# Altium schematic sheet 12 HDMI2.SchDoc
size 297 x 209 mm
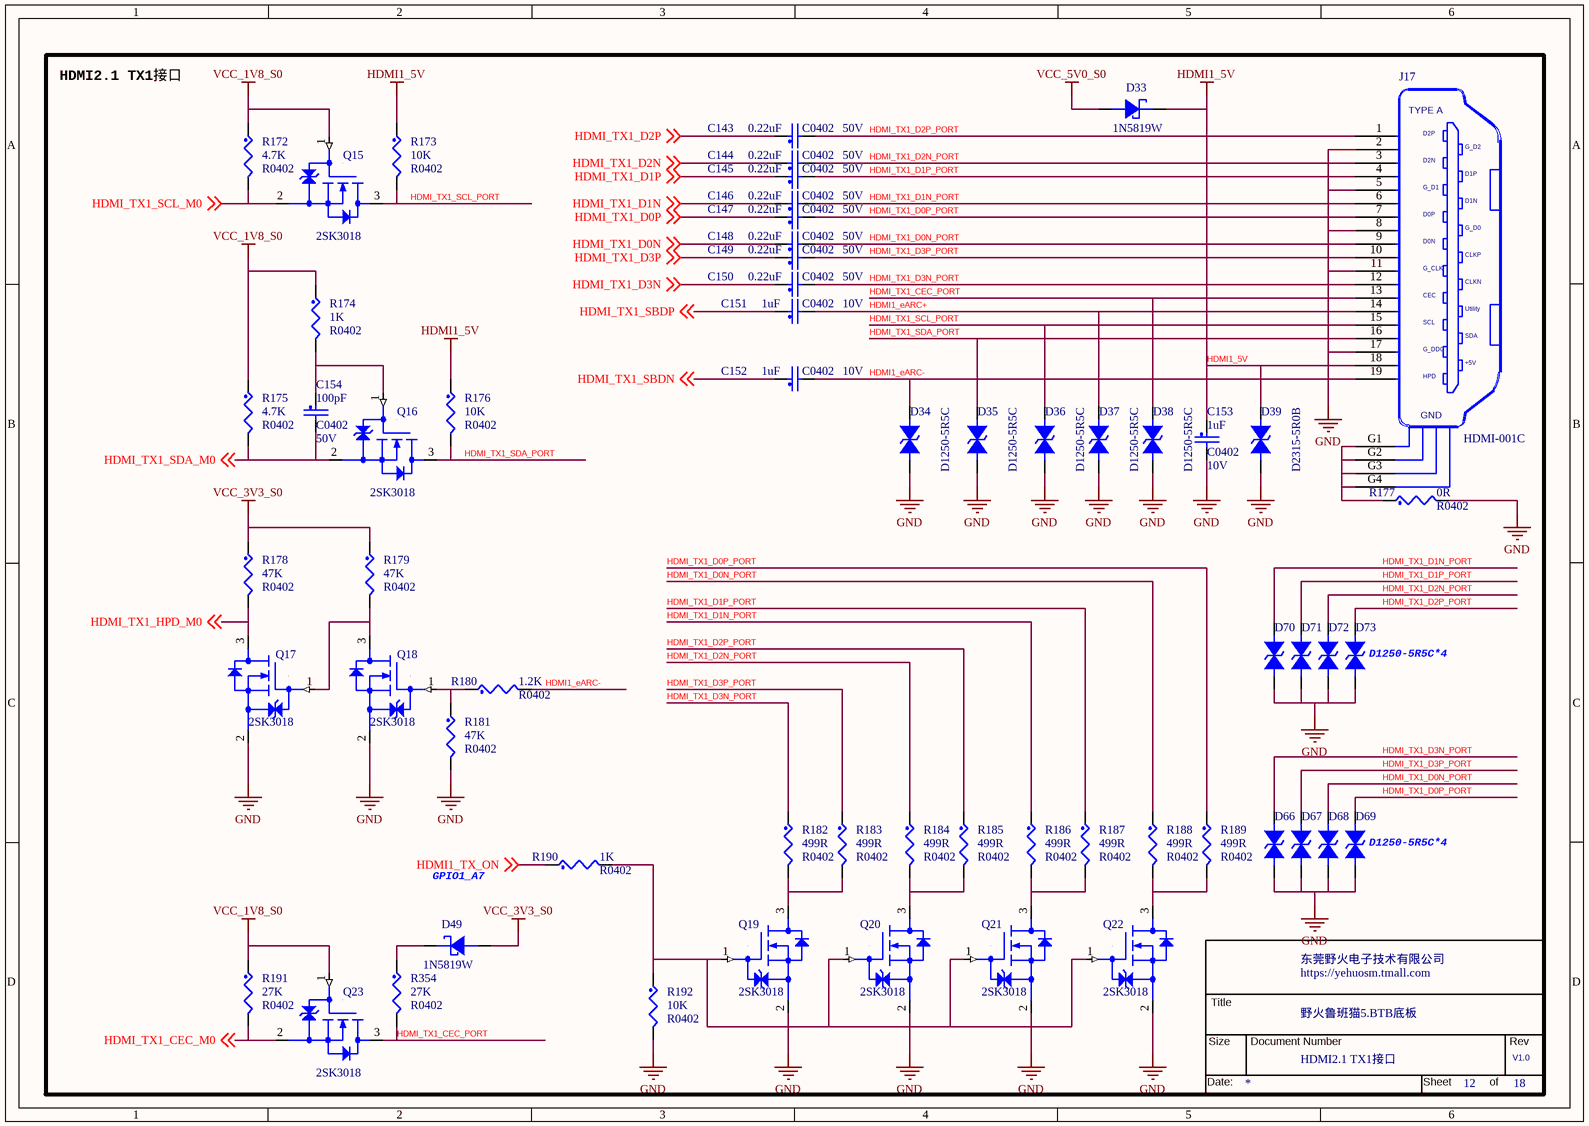
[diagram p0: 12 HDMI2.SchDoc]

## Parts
*  Doc: HDMI2.1 TX1接口  RevCode: V1.0  Title: 野火鲁班猫5.BTB底板  OrgName: 东莞野火电子技术有限公司  Page Number: 12  Page Count: 18  (hidden comment: TitleBlock_YHSCH)  (graphical)
C143  0.22uF  Voltage: 50V  [C0402]
C144  0.22uF  Voltage: 50V  [C0402]
C145  0.22uF  Voltage: 50V  [C0402]
C146  0.22uF  Voltage: 50V  [C0402]
C147  0.22uF  Voltage: 50V  [C0402]
C148  0.22uF  Voltage: 50V  [C0402]
C149  0.22uF  Voltage: 50V  [C0402]
C150  0.22uF  Voltage: 50V  [C0402]
C151  1uF  Voltage: 10V  [C0402]
C152  1uF  Voltage: 10V  [C0402]
C153  1uF  Voltage: 10V  [C0402]
C154  100pF  Voltage: 50V  [C0402]
D33  1N5819W  [SOD-123]
D34  D1250-5R5C  [D0603/SMD]
D35  D1250-5R5C  [D0603/SMD]
D36  D1250-5R5C  [D0603/SMD]
D37  D1250-5R5C  [D0603/SMD]
D38  D1250-5R5C  [D0603/SMD]
D39  D2315-5R0B  [D0603/SMD]
D49  1N5819W  [SOD-123]
D66  D1250-5R5C  [D0603/SMD]  (value not drawn)
D67  D1250-5R5C  [D0603/SMD]  (value not drawn)
D68  D1250-5R5C  [D0603/SMD]  (value not drawn)
D69  D1250-5R5C  [D0603/SMD]  (value not drawn)
D70  D1250-5R5C  [D0603/SMD]  (value not drawn)
D71  D1250-5R5C  [D0603/SMD]  (value not drawn)
D72  D1250-5R5C  [D0603/SMD]  (value not drawn)
D73  D1250-5R5C  [D0603/SMD]  (value not drawn)
J17  HDMI-001C  [HDMI-SMD]
Q15  2SK3018  [SOT23]
Q16  2SK3018  [SOT23]
Q17  2SK3018  [SOT23]
Q18  2SK3018  [SOT23]
Q19  2SK3018  [SOT23]
Q20  2SK3018  [SOT23]
Q21  2SK3018  [SOT23]
Q22  2SK3018  [SOT23]
Q23  2SK3018  [SOT23]
R172  4.7K  [R0402]
R173  10K  [R0402]
R174  1K  [R0402]
R175  4.7K  [R0402]
R176  10K  [R0402]
R177  0R  [R0402]
R178  47K  [R0402]
R179  47K  [R0402]
R180  1.2K  [R0402]
R181  47K  [R0402]
R182  499R  [R0402]
R183  499R  [R0402]
R184  499R  [R0402]
R185  499R  [R0402]
R186  499R  [R0402]
R187  499R  [R0402]
R188  499R  [R0402]
R189  499R  [R0402]
R190  1K  [R0402]
R191  27K  [R0402]
R192  10K  [R0402]
R354  27K  [R0402]

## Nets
GND: C153.2 D34.1 D35.1 D36.1 D37.1 D38.1 D39.1 D66.1 D67.1 D68.1 D69.1 D70.1 D71.1 D72.1 D73.1 J17.2 J17.5 J17.8 J17.11 J17.17 Q17.2(SOURCE) Q18.2(SOURCE) Q19.2(SOURCE) Q20.2(SOURCE) Q21.2(SOURCE) Q22.2(SOURCE) R177.2 R181.2 R192.2
HDMI1_5V: C153.1 D33.1 D39.2 J17.18 R173.1 R176.1
VCC_1V8_S0: Q15.1(GATE) Q23.1(GATE) R172.1 R174.1 R175.1 R191.1
VCC_3V3_S0: D49.2 R178.1 R179.1
VCC_5V0_S0: D33.2
HDMI1_eARC+: C151.2 D37.2 J17.14
HDMI1_eARC-: C152.2 D34.2 J17.19 R180.2
HDMI1_TX_ON: R190.1 ; off-sheet HDMI1_TX_ON
HDMI_TX1_CEC_M0: Q23.2(SOURCE) R191.2 ; off-sheet HDMI_TX1_CEC_M0
HDMI_TX1_CEC_PORT: D38.2 J17.13 Q23.3(DRAIN) R354.2
HDMI_TX1_D0N: C148.1 ; off-sheet HDMI_TX1_D0N
HDMI_TX1_D0N_PORT: C148.2 D68.2 J17.9 R188.1
HDMI_TX1_D0P: C147.1 ; off-sheet HDMI_TX1_D0P
HDMI_TX1_D0P_PORT: C147.2 D69.2 J17.7 R189.1
HDMI_TX1_D1N: C146.1 ; off-sheet HDMI_TX1_D1N
HDMI_TX1_D1N_PORT: C146.2 D70.2 J17.6 R186.1
HDMI_TX1_D1P: C145.1 ; off-sheet HDMI_TX1_D1P
HDMI_TX1_D1P_PORT: C145.2 D71.2 J17.4 R187.1
HDMI_TX1_D2N: C144.1 ; off-sheet HDMI_TX1_D2N
HDMI_TX1_D2N_PORT: C144.2 D72.2 J17.3 R184.1
HDMI_TX1_D2P: C143.1 ; off-sheet HDMI_TX1_D2P
HDMI_TX1_D2P_PORT: C143.2 D73.2 J17.1 R185.1
HDMI_TX1_D3N: C150.1 ; off-sheet HDMI_TX1_D3N
HDMI_TX1_D3N_PORT: C150.2 D66.2 J17.12 R182.1
HDMI_TX1_D3P: C149.1 ; off-sheet HDMI_TX1_D3P
HDMI_TX1_D3P_PORT: C149.2 D67.2 J17.10 R183.1
HDMI_TX1_HPD_M0: Q17.3(DRAIN) R178.2 ; off-sheet HDMI_TX1_HPD_M0
HDMI_TX1_SBDN: C152.1 ; off-sheet HDMI_TX1_SBDN
HDMI_TX1_SBDP: C151.1 ; off-sheet HDMI_TX1_SBDP
HDMI_TX1_SCL_M0: Q15.2(SOURCE) R172.2 ; off-sheet HDMI_TX1_SCL_M0
HDMI_TX1_SCL_PORT: D36.2 J17.15 Q15.3(DRAIN) R173.2
HDMI_TX1_SDA_M0: C154.2 Q16.2(SOURCE) R175.2 ; off-sheet HDMI_TX1_SDA_M0
HDMI_TX1_SDA_PORT: D35.2 J17.16 Q16.3(DRAIN) R176.2
NetC154_1: C154.1 Q16.1(GATE) R174.2
NetD49_1: D49.1 R354.1
NetJ17_G1: J17.G1 J17.G2 J17.G3 J17.G4 R177.1
NetQ17_1: Q17.1(GATE) Q18.3(DRAIN) R179.2
NetQ18_1: Q18.1(GATE) R180.1 R181.1
NetQ19_1: Q19.1(GATE) Q20.1(GATE) Q21.1(GATE) Q22.1(GATE) R190.2 R192.1
NetQ19_3: Q19.3(DRAIN) R182.2 R183.2
NetQ20_3: Q20.3(DRAIN) R184.2 R185.2
NetQ21_3: Q21.3(DRAIN) R186.2 R187.2
NetQ22_3: Q22.3(DRAIN) R188.2 R189.2

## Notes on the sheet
- HDMI2.1 TX1接口
- (near D73) D1250-5R5C*4
- GPIO1_A7
- (near D69) D1250-5R5C*4

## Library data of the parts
* = TitleBlock_YHSCH: Cage Code: 1
C143-C150 = CAP_NP: CLASS: DISCRETE; 生命周期: 量产; 价格: 0.074942; 规格书: 太诱-贴片电容.pdf; 类别: 贴片电容0402; 品牌: 太诱; 条码: EBF29060266; 规格编号: UMK105BJ224MV-F; 规格: 贴片电容0.22uF 20% 50V X5R 0402
C151-C153 = CAP_NP: CLASS: DISCRETE; 生命周期: 量产; 价格: 0.01191; 规格书: 风华电容.pdf; 类别: 贴片电容0402; 品牌: 风华; 条码: EBF29060121; 规格编号: 0402X105K100NT; 规格: 贴片电容1uF 10% 10V X5R 0402
C154 = CAP_NP: CLASS: DISCRETE; 生命周期: 量产; 价格: 0.034837; 规格书: 村田040系列贴片电容.pdf; 类别: 贴片电容0402; 品牌: 村田; 条码: EBF29060302; 规格编号: GRT1555C1H101JA; 规格: 贴片电容100pF 5% 50V C0G 0402
D33 = DIODE_SCHTKY: CLASS: IC; 丝印: SL; 生命周期: 量产; 价格: 0.175675; 规格书: 1N5819W.pdf; 类别: 贴片肖特基二极管; 品牌: 台湾迪嘉; 条码: EBF29140016; 规格: 肖特基二极管 直流反向耐压40V 平均整流电流1A 正向压降0.6V@1A SOD-123
D34-D38 = DIODE BI-DIR TRIG: PCB Footprint: R0201; 备注: 应用于HDMI2.1; 生命周期: 量产; 规格书: 千虹_D1250-5R5C.pdf; 类别: 贴片ESD; 品牌: 千虹; 条码: EBFCIS240604160037; 规格: 防静电保护ESD二极管 反向工作电压5.5V 击穿电压6V 钳位电压10.5V 结电容Cj 0.17pF
D39 = DIODE BI-DIR TRIG: PCB Footprint: esd0402; 备注: 通用; 生命周期: 量产; 规格书: 千虹_D2315-5R0B.pdf; 类别: 贴片ESD; 品牌: 千虹; 条码: EBFCIS240517170922; 规格: 防静电保护ESD二极管 反向工作电压5V 击穿电压7V 钳位电压10.5V 结电容Cj 0.3pF
D49 = DIODE_SCHTKY: CLASS: IC; 规格: 肖特基二极管 直流反向耐压40V 平均整流电流1A 正向压降0.6V@1A SOD-123; 条码: EBF29140016; 品牌: 台湾迪嘉; 类别: 贴片肖特基二极管; 规格书: 1N5819W.pdf; 价格: 0.175675; 生命周期: 量产; 丝印: SL
D66-D73 = DIODE BI-DIR TRIG: PCB Footprint: R0201; 规格: 防静电保护ESD二极管 反向工作电压5.5V 击穿电压6V 钳位电压10.5V 结电容Cj 0.17pF; 条码: EBFCIS240604160037; 品牌: 千虹; 类别: 贴片ESD; 规格书: 千虹_D1250-5R5C.pdf; 生命周期: 量产; 备注: 应用于HDMI2.1
J17 = HDMI-001C: VPN: 1166-2C105-211; Vendor: Comtek; OriginalSymbolOrigin: (-200,650); CLASS: IO; 规格: HDMI立式; 条码: EBF29040081; 品牌: 讯普; 类别: HDMI连接器; 规格书: HDMI-001C.pdf; 生命周期: 量产
Q15 Q16 Q18 = 2SK3018: CLASS: IC; 规格: N沟道MOS 导通电阻8Ω 电流10mA 0.8V可驱动; 条码: EBF29280009; 品牌: 江苏长电; 类别: N-MOS; 规格书: 长电科技-2SK3018.pdf; 价格: 0.120725; 生命周期: 量产; 丝印: KN
Q17 Q19-Q23 = 2SK3018: CLASS: IC; 丝印: KN; 生命周期: 量产; 价格: 0.120725; 规格书: 长电科技-2SK3018.pdf; 类别: N-MOS; 品牌: 江苏长电; 条码: EBF29280009; 规格: N沟道MOS 导通电阻8Ω 电流10mA 0.8V可驱动
R172 R175 = RES: CLASS: DISCRETE; 生命周期: 量产; 规格书: 合科泰-RI系列电阻.pdf; 类别: 贴片电阻0402; 品牌: 合科泰; 条码: EBF29070047; 规格编号: RI0402L4701FT; 规格: 贴片电阻4.7K 1% 1/16W 0402
R173 R176 R192 = RES: CLASS: DISCRETE; 生命周期: 量产; 价格: 0.002773; 规格书: 厚声-无铅厚膜电阻.pdf; 类别: 贴片电阻0402; 品牌: 厚声; 条码: EBF29070046; 规格编号: 0402WGF1002TCE; 规格: 贴片电阻10K 1% 1/16W 0402
R174 = RES: CLASS: DISCRETE; 生命周期: 量产; 规格书: 合科泰-RI系列电阻.pdf; 类别: 贴片电阻0402; 品牌: 合科泰; 条码: EBF29070050; 规格编号: RI0402L1001FT; 规格: 贴片电阻1K 1% 1/16W 0402
R177 = RES: CLASS: DISCRETE; 规格: 贴片电阻0R 1% 1/16W 0402; 规格编号: RI0402L000FT; 条码: EBF29070049; 品牌: 合科泰; 类别: 贴片电阻0402; 规格书: 合科泰-RI系列电阻.pdf; 生命周期: 量产
R178 R179 = RES: CLASS: DISCRETE; 生命周期: 量产; 规格书: 厚声-无铅厚膜电阻.pdf; 类别: 贴片电阻0402; 品牌: 厚声; 条码: EBF29070247; 规格编号: 0402WGF4702TCE; 规格: 贴片电阻47K 1% 1/16W 0402
R180 = RES: CLASS: DISCRETE; 价格: 0.001447; 规格书: 厚声-无铅厚膜电阻.pdf; 类别: 贴片电阻0402; 品牌: 厚声; 条码: EBFCIS221112112140; 规格编号: 0402WGF1201TCE; 规格: 贴片电阻1.2K 1% 1/16W 0402; 生命周期: 量产
R181 = RES: CLASS: DISCRETE; 规格: 贴片电阻47K 1% 1/16W 0402; 规格编号: 0402WGF4702TCE; 条码: EBF29070247; 品牌: 厚声; 类别: 贴片电阻0402; 规格书: 厚声-无铅厚膜电阻.pdf; 生命周期: 量产
R182 R184 R187 R189 = RES: CLASS: DISCRETE; 生命周期: 量产; 价格: 0.003791; 规格书: 厚声-无铅厚膜电阻.pdf; 类别: 贴片电阻0402; 品牌: 厚声; 条码: EBF29070287; 规格编号: 0402WGF4990TCE; 规格: 贴片电阻499R 1% 1/16W 0402
R183 R185 R186 R188 = RES: CLASS: DISCRETE; 规格: 贴片电阻499R 1% 1/16W 0402; 规格编号: 0402WGF4990TCE; 条码: EBF29070287; 品牌: 厚声; 类别: 贴片电阻0402; 规格书: 厚声-无铅厚膜电阻.pdf; 价格: 0.003791; 生命周期: 量产
R190 = RES: CLASS: DISCRETE; 规格: 贴片电阻1K 1% 1/16W 0402; 规格编号: RI0402L1001FT; 条码: EBF29070050; 品牌: 合科泰; 类别: 贴片电阻0402; 规格书: 合科泰-RI系列电阻.pdf; 生命周期: 量产
R191 = RES: CLASS: DISCRETE; 生命周期: 量产; 价格: 0.007054; 规格书: YAGEO国巨厚膜无铅电阻.pdf; 类别: 贴片电阻0402; 品牌: 国巨; 条码: EBF29070003; 规格编号: AC0402FR-0727KL; 规格: 贴片电阻27K 1% 1/16W 0402
R354 = RES: CLASS: DISCRETE; 规格: 贴片电阻27K 1% 1/16W 0402; 规格编号: AC0402FR-0727KL; 条码: EBF29070003; 品牌: 国巨; 类别: 贴片电阻0402; 规格书: YAGEO国巨厚膜无铅电阻.pdf; 价格: 0.007054; 生命周期: 量产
